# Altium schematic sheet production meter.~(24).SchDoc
size A4
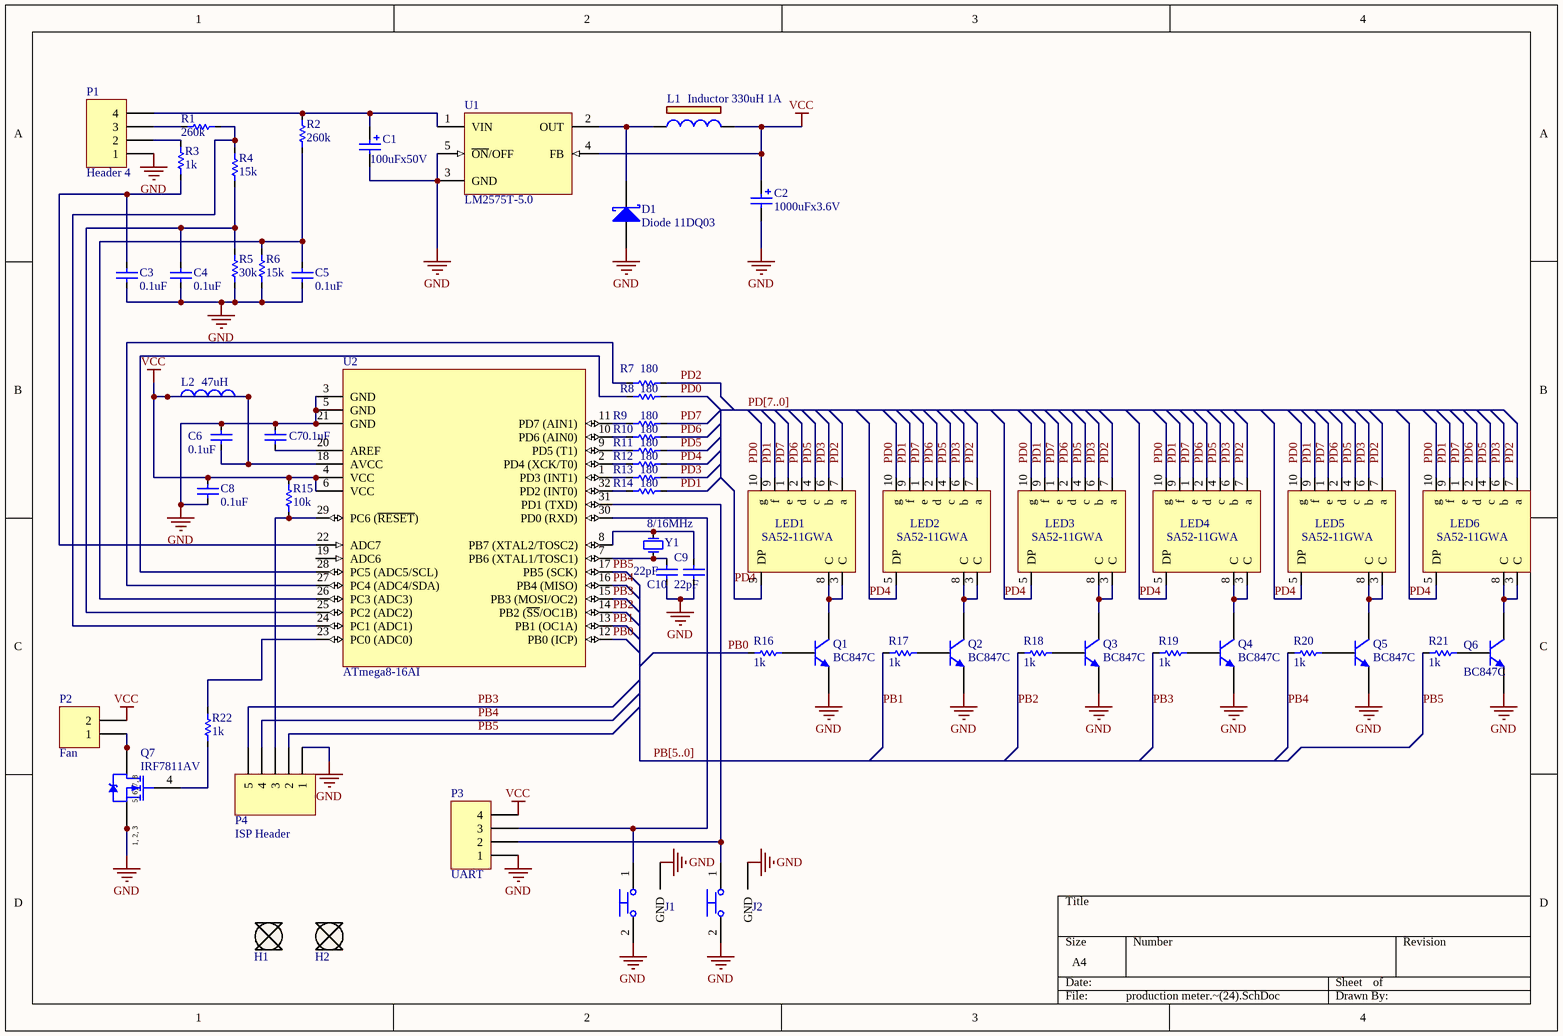
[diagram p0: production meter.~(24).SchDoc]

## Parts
C1  100uFx50V  [CEd8p5]
C2  1000uFx3.6V  [CEd10p3.5]
C3  0.1uF  [C0805\2P]
C4  0.1uF  [C0805\2P]
C5  0.1uF  [C0805\2P]
C6  0.1uF  [C0805\2P]
C7  0.1uF  [C0805\2P]
C8  0.1uF  [C0805\2P]
C9  22pF  [C0805\2P]
C10  22pF  [C0805\2P]
D1  Diode 11DQ03  [DIO10.46-5.3x2.8]
H1  Hole_3mm  [F3.5X7.5_Met_NH]  (value not drawn)
H2  Hole_3mm  [F3.5X7.5_Met_NH]  (value not drawn)
J1  swich push 6x3.5x2.5mm 160gf 50mA/12DVC  [M/T1600-EV]  (value not drawn)
J2  swich push 6x3.5x2.5mm 160gf 50mA/12DVC  [M/T1600-EV]  (value not drawn)
L1  Inductor 330uH 1A  [Inductor footprint]
L2  47uH  [LL0805\2P]
LED1  SA52-11GWA  [SA52-11GWA]
LED2  SA52-11GWA  [SA52-11GWA]
LED3  SA52-11GWA  [SA52-11GWA]
LED4  SA52-11GWA  [SA52-11GWA]
LED5  SA52-11GWA  [SA52-11GWA]
LED6  SA52-11GWA  [SA52-11GWA]
P1  Header 4  [HDR1X4]
P2  Fan  [HDR1X2]
P3  UART  [HDR1X4]
P4  ISP Header  [HDR1X5]
Q1  BC847C  [SOT23_L]
Q2  BC847C  [SOT23_L]
Q3  BC847C  [SOT23_L]
Q4  BC847C  [SOT23_L]
Q5  BC847C  [SOT23_L]
Q6  BC847C  [SOT23_L]
Q7  IRF7811AV  [SO-8_N]
R1  260k  [R0805\2P]
R2  260k  [R0805\2P]
R3  1k  [R0805\2P]
R4  15k  [R0805\2P]
R5  30k  [R0805\2P]
R6  15k  [R0805\2P]
R7  180  [R0805\2P]
R8  180  [R0805\2P]
R9  180  [R0805\2P]
R10  180  [R0805\2P]
R11  180  [R0805\2P]
R12  180  [R0805\2P]
R13  180  [R0805\2P]
R14  180  [R0805\2P]
R15  10k  [R0805\2P]
R16  1k  [R0805\2P]
R17  1k  [R0805\2P]
R18  1k  [R0805\2P]
R19  1k  [R0805\2P]
R20  1k  [R0805\2P]
R21  1k  [R0805\2P]
R22  1k  [R0805\2P]
U1  LM2575T-5.0  [T05A]
U2  ATmega8-16AI  [32A_N]
Y1  XTAL  [XTAL_AXIAL_L11W4.6P4.9]  (value not drawn)

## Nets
GND: C1.2 C2.2 C3.2 C4.2 C5.2 C6.1 C7.1 C8.2 C9.1 C10.1 D1.1(A) J1.2 J1.3(GND) J2.2 J2.3(GND) P1.1 P3.1 P4.1 Q1.2(E) Q2.2(E) Q3.2(E) Q4.2(E) Q5.2(E) Q6.2(E) Q7.1(S) Q7.2(S) Q7.3(S) R5.1 R6.1 U1.3(GND) U1.5(~{ON}/OFF) U2.3(GND) U2.5(GND) U2.21(GND)
VCC: C2.1 C6.2 C8.1 L1.2 L2.1 L2.2 P2.2 P3.4 R15.1 U1.4(FB) U2.4(VCC) U2.6(VCC) U2.18(AVCC)
PB0: R16.1 U2.12(PB0_(ICP))
PB1: R17.1 U2.13(PB1_(OC1A))
PB2: R18.1 U2.14(PB2_(~{SS}/OC1B))
PB3: P4.5 R19.1 U2.15(PB3_(MOSI/OC2))
PB4: P4.4 R20.1 U2.16(PB4_(MISO))
PB5: P4.2 R21.1 U2.17(PB5_(SCK))
PD0: LED1.10(g) LED2.10(g) LED3.10(g) LED4.10(g) LED5.10(g) LED6.10(g) R8.2
PD1: LED1.9(f) LED2.9(f) LED3.9(f) LED4.9(f) LED5.9(f) LED6.9(f) R14.2
PD2: LED1.7(a) LED2.7(a) LED3.7(a) LED4.7(a) LED5.7(a) LED6.7(a) R7.2
PD3: LED1.6(b) LED2.6(b) LED3.6(b) LED4.6(b) LED5.6(b) LED6.6(b) R13.2
PD4: LED1.5(DP) LED2.5(DP) LED3.5(DP) LED4.5(DP) LED5.5(DP) LED6.5(DP) R12.2
PD5: LED1.4(c) LED2.4(c) LED3.4(c) LED4.4(c) LED5.4(c) LED6.4(c) R11.2
PD6: LED1.2(d) LED2.2(d) LED3.2(d) LED4.2(d) LED5.2(d) LED6.2(d) R10.2
PD7: LED1.1(e) LED2.1(e) LED3.1(e) LED4.1(e) LED5.1(e) LED6.1(e) R9.2
NetC1_1: C1.1 P1.4 R2.2 U1.1(VIN)
NetC3_1: C3.1 R3.1 U2.22(ADC7)
NetC4_1: C4.1 R4.1 R5.2 U2.25(PC2_(ADC2))
NetC5_1: C5.1 R2.1 R6.2 U2.26(PC3_(ADC3))
NetC7_2: C7.2 U2.20(AREF)
NetC9_2: C9.2 U2.8(PB7_(XTAL2/TOSC2)) Y1.2(OSC2)
NetC10_2: C10.2 U2.7(PB6_(XTAL1/TOSC1)) Y1.1(OSC1)
NetD1_2: D1.2(K) L1.1 U1.2(OUT)
NetJ1_1: J1.1 P3.3 U2.30(PD0_(RXD))
NetJ2_1: J2.1 P3.2 U2.31(PD1_(TXD))
NetLED1_3: LED1.3(C) LED1.8(C) Q1.3(C)
NetLED2_3: LED2.3(C) LED2.8(C) Q2.3(C)
NetLED3_3: LED3.3(C) LED3.8(C) Q3.3(C)
NetLED4_3: LED4.3(C) LED4.8(C) Q4.3(C)
NetLED5_3: LED5.3(C) LED5.8(C) Q5.3(C)
NetLED6_3: LED6.3(C) LED6.8(C) Q6.3(C)
NetP1_2: P1.2 R3.2
NetP1_3: P1.3 R1.2
NetP2_1: P2.1 Q7.5(D) Q7.6(D) Q7.7(D) Q7.8(D)
NetP4_3: P4.3 R15.2 U2.29(PC6_(~{RESET}))
NetQ1_1: Q1.1(B) R16.2
NetQ2_1: Q2.1(B) R17.2
NetQ3_1: Q3.1(B) R18.2
NetQ4_1: Q4.1(B) R19.2
NetQ5_1: Q5.1(B) R20.2
NetQ6_1: Q6.1(B) R21.2
NetQ7_4: Q7.4(G) R22.2
NetR1_1: R1.1 R4.2 U2.24(PC1_(ADC1))
NetR7_1: R7.1 U2.27(PC4_(ADC4/SDA))
NetR8_1: R8.1 U2.28(PC5_(ADC5/SCL))
NetR9_1: R9.1 U2.11(PD7_(AIN1))
NetR10_1: R10.1 U2.10(PD6_(AIN0))
NetR11_1: R11.1 U2.9(PD5_(T1))
NetR12_1: R12.1 U2.2(PD4_(XCK/T0))
NetR13_1: R13.1 U2.1(PD3_(INT1))
NetR14_1: R14.1 U2.32(PD2_(INT0))
NetR22_1: R22.1 U2.23(PC0_(ADC0))

Not connected (* = marked no-connect by the designer): H1 0; H2 0; U2 19(ADC6)

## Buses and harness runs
bus PB[5..0]
bus PD[7..0]

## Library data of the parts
C1 C2 = Cap_Elect: Electrolytic capacitor
C3-C10 = Cap_Cer: Capacitor ceramic
D1 = Diode 11DQ03: Schottky Rectifier
J1 J2 = swich push 6x3.5x2.5mm 160gf 50mA/12DVC: 6x3.5x2.5mm 160gf 50mA/12DVC
L1 = Inductor 330uH 1A_1
L2 = Inductor
P1 P3 = Header 4: Header, 4-Pin
P2 = Header 2: Header, 2-Pin
P4 = Header 5: Header, 5-Pin
Q1-Q6 = BC847C: NPN General-purpose Transistor
Q7 = IRF7811AV: HEXFET Power MOSFET
R1-R22 = Res: Resistor
U1 = LM2575T-5.0: SIMPLE SWITCHER 1A Step-Down Voltage Regulator; Manufacturer: National Semiconductor; PackageTopMarking: NSUZXYTT*LM2575T*-5.0 P+; PowerWise: N
U2 = ATmega8-16AI: 8-Bit AVR Microcontroller with 8K Bytes of In-System Programmable Flash Memory
Y1 = XTAL: Quartz Crystal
